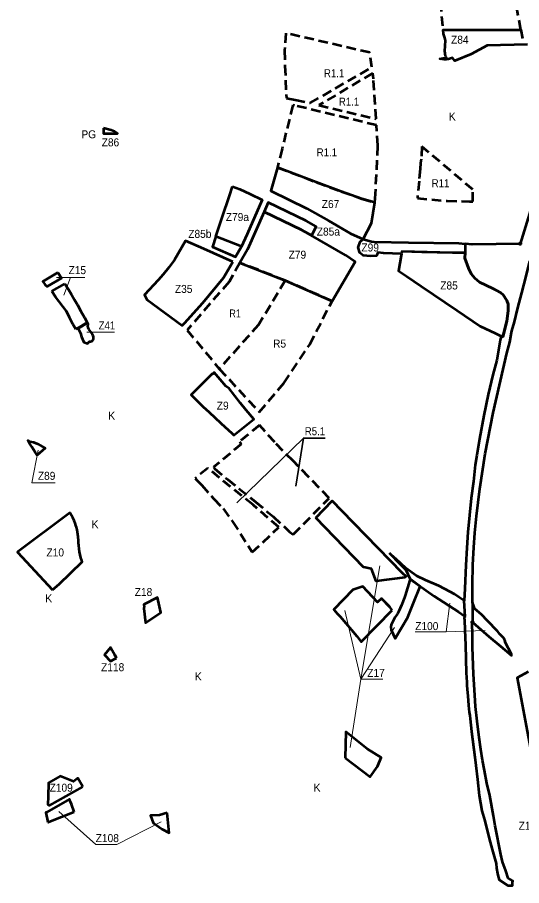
# Model space of a CAD drawing. Extents: x -650246 to -642674, y -1074280 to -1066767.
# Drawn here: x -646713 to -645200, y -1073293 to -1070690 of the extents above; entities that cross this region are included whole.
import ezdxf

# ---------------------------------------------------------------- set-up
doc = ezdxf.new("R2010")
doc.units = 0
doc.header["$LTSCALE"] = 9.6
doc.header["$PDMODE"] = 32
doc.header["$PDSIZE"] = 4.8
doc.linetypes.add('MEDIUM_DASHED', pattern=[4.5, 3, -1.5])
for name, color, linetype, lineweight in [('44', 7, 'Continuous', 53), ('45', 7, 'Continuous', 53), ('46', 7, 'Continuous', 13), ('48', 7, 'Continuous', 13), ('60', 7, 'Continuous', 35), ('61', 7, 'MEDIUM_DASHED', 53), ('62', 7, 'Continuous', 35)]:
    doc.layers.add(name, color=color, linetype=linetype, lineweight=lineweight)

msp = doc.modelspace()

# ---------------------------------------------------------------- linework, layer by layer
at = {"layer": '44'}
msp.add_line((-645369.665, -1071395.694), (-645370.24, -1071411.83), dxfattribs=at)
for points in [[(-645182, -1070771), (-645303, -1070774), (-645351, -1070800), (-645400.05, -1070819.84), (-645407.37, -1070810.95), (-645419.18, -1070815.44), (-645426.36, -1070815.78), (-645432.07, -1070816.05), (-645445.81, -1070814.06), (-645429.993, -1070810.647), (-645424.969, -1070809.563), (-645428.39, -1070806.09), (-645430, -1070790.68), (-645428.73, -1070758.67), (-645430.84, -1070751.43), (-645434.53, -1070738.77), (-645435.711, -1070727.497), (-645202.41, -1070726.571), (-645197.539, -1070753.128)], [(-645078.23, -1070915.65), (-645092.67, -1070979.52), (-645176.14, -1071277.26), (-645204.341, -1071368.19)], [(-645407.045, -1071395.646), (-645499.65, -1071393.3), (-645558.872, -1071391.801), (-645560.11, -1071398.7), (-645614.201, -1071396.844), (-645631.44, -1071394.9), (-645635.795, -1071404.403), (-645653.742, -1071405.36), (-645675.177, -1071403.922), (-645685.098, -1071395.824), (-645690.677, -1071379.721), (-645684.785, -1071362.539), (-645674.947, -1071355.071), (-645650.28, -1071362.07), (-645642.431, -1071362.259), (-645539.738, -1071364.092)], [(-645539.738, -1071364.092), (-645388.619, -1071366.991), (-645369.696, -1071368.676)], [(-645369.67, -1071368.678), (-645369.665, -1071395.694), (-645407.045, -1071395.646)], [(-645204.341, -1071368.19), (-645348.55, -1071370.559), (-645369.67, -1071368.678)], [(-645222.48, -1071606.08), (-645211.27, -1071560.01), (-645199.61, -1071515.68), (-645186.67, -1071465.55), (-645175.06, -1071420.93), (-645167.58, -1071421.19), (-645167.37, -1071415.2), (-645163.56, -1071415.3), (-645164.76, -1071401.79), (-645166.34, -1071384.07)], [(-645560.94, -1071403.441), (-645569.07, -1071449.88), (-645545.817, -1071465.611)], [(-645370.24, -1071411.83), (-645369.665, -1071395.694), (-645407.045, -1071395.646), (-645558.872, -1071391.801), (-645560.11, -1071398.7), (-645560.94, -1071403.441)], [(-645370.24, -1071411.83), (-645359.64, -1071442), (-645351.06, -1071458.3), (-645340.16, -1071471.63), (-645326.29, -1071483.41), (-645286.62, -1071502.67), (-645278.52, -1071506.12)], [(-645326.29, -1071483.41), (-645340.16, -1071471.63), (-645351.06, -1071458.3), (-645359.64, -1071442), (-645370.24, -1071411.83)], [(-645545.817, -1071465.611), (-645501.37, -1071495.68), (-645393.34, -1071568.75)], [(-645279.531, -1071636.404), (-645261.094, -1071645.025), (-645256.02, -1071647.398), (-645244.81, -1071600.61), (-645240.26, -1071569.52), (-645240.82, -1071549.6), (-645244.4, -1071538.48), (-645255.51, -1071521.55), (-645262.36, -1071515.72), (-645286.62, -1071502.67), (-645326.29, -1071483.41)], [(-645278.52, -1071506.12), (-645262.36, -1071515.72), (-645255.51, -1071521.55), (-645244.4, -1071538.48), (-645240.82, -1071549.6), (-645240.26, -1071569.52), (-645244.81, -1071600.61), (-645256.02, -1071647.398), (-645261.094, -1071645.025)], [(-645393.34, -1071568.75), (-645324.17, -1071615.53), (-645279.531, -1071636.404)], [(-645347.551, -1072443.527), (-645347.677, -1072391.355), (-645346.62, -1072330.914), (-645343.458, -1072278.998), (-645339.908, -1072235.158), (-645335.367, -1072185.207), (-645325.498, -1072102.789), (-645309.01, -1071998.147), (-645285.617, -1071875.733), (-645244.798, -1071696.585), (-645235.793, -1071663.703), (-645230.436, -1071634.261), (-645227.905, -1071625.277), (-645222.48, -1071606.08)], [(-645261.094, -1071645.025), (-645264.841, -1071657.687), (-645269.077, -1071687.396), (-645274.868, -1071717.176), (-645286.175, -1071761.228), (-645300.076, -1071820.179), (-645313.153, -1071883.081)], [(-645313.153, -1071883.081), (-645326.343, -1071952.807), (-645334.118, -1072001.954), (-645339.455, -1072031.565), (-645344.819, -1072081.225), (-645351.358, -1072130.815), (-645361.317, -1072232.824), (-645364.435, -1072280.268), (-645366.951, -1072331.609), (-645370.624, -1072401.447), (-645372.228, -1072438.764)], [(-645369.364, -1072485.931), (-645372.228, -1072438.764), (-645373.099, -1072438.135), (-645387.894, -1072427.453), (-645401.441, -1072419.033), (-645414.631, -1072411.611), (-645448.831, -1072394.325), (-645488.64, -1072376.782), (-645515.437, -1072363.447), (-645547.593, -1072340.827), (-645577.33, -1072312.704), (-645579.217, -1072312.425), (-645596.405, -1072296.114)], [(-645596.405, -1072296.114), (-645564.4, -1072328.61), (-645547.72, -1072346.19), (-645534.301, -1072374.332), (-645462.646, -1072425.015)], [(-645462.646, -1072425.015), (-645389.731, -1072471.612), (-645372.013, -1072484.069), (-645369.364, -1072485.931)], [(-645339.904, -1072462.677), (-645342.953, -1072455.042), (-645347.551, -1072443.527), (-645347.292, -1072502.877)], [(-645228.96, -1072600.865), (-645249.9, -1072561.25), (-645248.967, -1072559.511), (-645252.768, -1072552.178), (-645265.009, -1072538.358), (-645272.276, -1072530.154), (-645302.303, -1072499.014), (-645320.805, -1072479.495), (-645339.904, -1072462.677)], [(-645369.364, -1072485.931), (-645372.72, -1072490.314), (-645370.928, -1072496.619), (-645370.755, -1072525.734), (-645368.173, -1072571.881), (-645366.022, -1072654.462), (-645364.524, -1072682.575), (-645364.786, -1072692.977), (-645362.708, -1072714.781)], [(-645338.023, -1072755.969), (-645339.96, -1072721.587), (-645344.152, -1072658.857), (-645347.795, -1072577.893), (-645347.214, -1072540.97), (-645348.253, -1072505.583), (-645347.292, -1072502.877)], [(-645347.292, -1072502.877), (-645346.093, -1072503.921), (-645298.498, -1072545.352)], [(-645298.498, -1072545.352), (-645263.217, -1072574.314), (-645230.845, -1072602.888), (-645228.96, -1072600.865)], [(-645362.708, -1072714.781), (-645361.874, -1072723.527), (-645359.76, -1072752.865), (-645357.272, -1072772.771), (-645355.121, -1072782.993)], [(-645317.65, -1072916.642), (-645322.284, -1072885.085), (-645327.091, -1072848.387), (-645333.718, -1072799.987), (-645338.023, -1072755.969)], [(-645355.121, -1072782.993), (-645354.019, -1072792.454), (-645350.822, -1072830.388), (-645340.345, -1072908.029), (-645337.34, -1072932.073), (-645332.517, -1072974.538), (-645327.554, -1073022.214), (-645319.052, -1073068.6), (-645310.558, -1073098.946), (-645297.395, -1073151.294), (-645288.647, -1073184.518), (-645276.125, -1073226.571), (-645275.269, -1073240.71), (-645272.747, -1073256.762), (-645271.518, -1073261.16)], [(-645304.24, -1072985.372), (-645311.772, -1072947.945), (-645317.65, -1072916.642)], [(-645257.842, -1073221.36), (-645262.388, -1073199.409), (-645279.878, -1073113.356), (-645284.269, -1073083.286), (-645295.788, -1073022.556), (-645304.24, -1072985.372)], [(-645237.524, -1073292.361), (-645227.744, -1073292.735), (-645227.199, -1073283.366), (-645226.847, -1073278.345), (-645239.9, -1073270.025), (-645247.051, -1073248.736), (-645257.842, -1073221.36)], [(-645271.518, -1073261.16), (-645267.525, -1073275.443), (-645241.72, -1073292.2), (-645237.524, -1073292.361)]]:
    msp.add_lwpolyline(points, dxfattribs=at)
for points in [[(-646454.59, -1071021.54), (-646454.59, -1071038), (-646412.54, -1071038.01), (-646415.61, -1071035.4), (-646421.58, -1071031.81), (-646430.91, -1071027.44)], [(-645829.706, -1071343.963), (-645816.714, -1071316.828), (-645846, -1071300), (-645960.34, -1071245.09), (-645972.422, -1071272.568), (-645859.986, -1071326.563)], [(-646117.031, -1071346.48), (-646127.301, -1071378.036), (-646058.719, -1071407.796), (-646051.148, -1071395.208), (-646040.084, -1071376.813)], [(-646652.18, -1071967.73), (-646629.655, -1071981.343), (-646653.198, -1072002.544), (-646657.32, -1071995.98), (-646658.79, -1071993.62), (-646669.31, -1071976.77), (-646676.79, -1071964.97), (-646681.07, -1071958.16), (-646675.99, -1071961.64), (-646663.87, -1071963.26)]]:
    msp.add_lwpolyline(points, close=True, dxfattribs=at)
at = {"layer": '44', "lineweight": 13}
for points in [[(-646599.686, -1072084.891), (-646669.193, -1072084.891), (-646650.508, -1071987.658)], [(-646599.686, -1072084.891), (-646669.193, -1072084.891), (-646650.508, -1071987.658)], [(-645519.31, -1072532.095), (-645425.882, -1072532.095), (-645415.202, -1072445.813), (-645425.882, -1072532.095), (-645309.26, -1072527.964)], [(-645519.31, -1072532.095), (-645425.882, -1072532.095), (-645415.202, -1072445.813), (-645425.882, -1072532.095), (-645309.26, -1072527.964)]]:
    msp.add_lwpolyline(points, dxfattribs=at)
at = {"layer": '44'}
for p in [(-645204.341, -1071368.19), (-645347.292, -1072502.877)]:
    msp.add_point(p, dxfattribs=at)
at = {"layer": '45'}
for p, q in [((-646609.21, -1071510.98), (-646570, -1071488.38)), ((-646609.21, -1071510.98), (-646570, -1071488.38)), ((-646417.787, -1072612.168), (-646414.77, -1072610.61))]:
    msp.add_line(p, q, dxfattribs=at)
for points in [[(-645674.947, -1071355.071), (-645650.09, -1071306.433), (-645640.737, -1071244.963), (-645678.86, -1071233.58), (-645741.09, -1071211.36), (-645816.47, -1071183.63), (-645932.502, -1071139.426), (-645952.419, -1071210.117), (-645844.079, -1071262.487), (-645778.69, -1071299.362), (-645713.428, -1071337.765)], [(-646067.097, -1071196.699), (-646044.944, -1071205.157), (-646015.387, -1071218.854), (-645978.403, -1071236.481), (-646023.652, -1071339.428), (-646035.241, -1071365.795), (-646040.084, -1071376.813), (-646117.031, -1071346.48), (-646098.66, -1071290.03), (-646076.713, -1071225.138)], [(-645768.62, -1071540.17), (-645699.825, -1071422.134), (-645728.054, -1071402.382), (-645806.036, -1071357.564), (-645859.986, -1071326.563), (-645972.422, -1071272.568), (-646022.073, -1071385.273), (-646044.948, -1071425.333), (-645909.13, -1071478.56)], [(-645768.62, -1071540.17), (-645699.825, -1071422.134), (-645728.054, -1071402.382), (-645806.036, -1071357.564), (-645859.986, -1071326.563), (-645972.422, -1071272.568), (-646022.073, -1071385.273), (-646044.948, -1071425.333), (-645909.13, -1071478.56)], [(-646066.165, -1071422.155), (-646153.5, -1071383.85), (-646208.577, -1071360.044), (-646241.68, -1071416.887), (-646258.487, -1071439.265), (-646275.615, -1071460.886), (-646289.976, -1071477.514), (-646330.914, -1071521.11), (-646324, -1071535), (-646217.978, -1071613.552), (-646211.407, -1071606.247), (-646156.471, -1071545.166), (-646094.063, -1071471.007)], [(-646066.165, -1071422.155), (-646153.5, -1071383.85), (-646208.577, -1071360.044), (-646241.68, -1071416.887), (-646258.487, -1071439.265), (-646275.615, -1071460.886), (-646289.976, -1071477.514), (-646330.914, -1071521.11), (-646324, -1071535), (-646217.978, -1071613.552), (-646211.407, -1071606.247), (-646156.471, -1071545.166), (-646094.063, -1071471.007)], [(-646591.65, -1071454.91), (-646635.79, -1071481.6), (-646629.37, -1071491.74), (-646623.18, -1071496.99), (-646580.58, -1071471.48)], [(-646591.65, -1071454.91), (-646635.79, -1071481.6), (-646629.37, -1071491.74), (-646623.18, -1071496.99), (-646580.58, -1071471.48)], [(-646502.39, -1071605.72), (-646530.27, -1071622.79), (-646522.99, -1071636.22), (-646520.32, -1071647.59), (-646513.43, -1071663.64), (-646502.53, -1071667.82), (-646496.06, -1071661.5), (-646492.89, -1071661.75), (-646490.07, -1071660.88), (-646487.36, -1071659.1), (-646485.29, -1071656.53), (-646484.15, -1071653.38), (-646483.97, -1071650.63), (-646484.38, -1071647.41), (-646485.2, -1071644.85), (-646486.31, -1071641.97), (-646487.56, -1071639.23), (-646497.83, -1071624.02), (-646499.829, -1071620.704), (-646500.289, -1071619.291), (-646500.83, -1071615.62), (-646500.34, -1071609.66)], [(-646502.39, -1071605.72), (-646530.27, -1071622.79), (-646522.99, -1071636.22), (-646520.32, -1071647.59), (-646513.43, -1071663.64), (-646502.53, -1071667.82), (-646496.06, -1071661.5), (-646492.89, -1071661.75), (-646490.07, -1071660.88), (-646487.36, -1071659.1), (-646485.29, -1071656.53), (-646484.15, -1071653.38), (-646483.97, -1071650.63), (-646484.38, -1071647.41), (-646485.2, -1071644.85), (-646486.31, -1071641.97), (-646487.56, -1071639.23), (-646497.83, -1071624.02), (-646499.829, -1071620.704), (-646500.289, -1071619.291), (-646500.83, -1071615.62), (-646500.34, -1071609.66)], [(-646102.04, -1071906.4), (-646068.317, -1071937.555), (-646062.91, -1071942.55), (-646002.93, -1071893.984), (-646026.64, -1071867.44), (-646043.49, -1071845.87), (-646077.32, -1071802.59), (-646087, -1071795), (-646104.5, -1071774.86), (-646122.16, -1071754.78), (-646127.12, -1071759.15), (-646127.84, -1071758.53), (-646191.57, -1071821.44), (-646174.69, -1071838.69), (-646156.59, -1071856.53), (-646137.74, -1071873.31)], [(-645817.219, -1072189.975), (-645768.649, -1072139.283), (-645740.45, -1072168.23), (-645559.34, -1072354.42), (-645546.82, -1072365.72), (-645550.41, -1072368.47), (-645636.37, -1072379.57), (-645650.78, -1072342.73), (-645674, -1072338), (-645789.298, -1072218.833)], [(-646606.848, -1072405.785), (-646587.666, -1072389.082), (-646518.208, -1072321.92), (-646519.417, -1072318.408), (-646522.007, -1072309.932), (-646524.282, -1072300.849), (-646526, -1072292.201), (-646527.5, -1072282.657), (-646528.566, -1072273.308), (-646529.182, -1072265.941), (-646529.607, -1072258.124), (-646530.188, -1072247.442), (-646530.892, -1072239.747), (-646531.93, -1072232.861), (-646533.286, -1072226.031), (-646535.344, -1072217.844), (-646536.772, -1072213.218), (-646539.168, -1072206.122), (-646539.168, -1072206.122), (-646542.484, -1072197.985), (-646546.09, -1072190.428), (-646549.793, -1072183.38), (-646554.56, -1072175.629), (-646555.051, -1072174.933), (-646563.299, -1072181.091), (-646710.684, -1072291.133), (-646712.634, -1072292.59)], [(-645503.98, -1072395.64), (-645532.75, -1072375.41), (-645535.05, -1072376.72), (-645549.6, -1072423.39), (-645551.54, -1072428.66), (-645559.92, -1072451.41), (-645568.38, -1072469.68), (-645572.13, -1072477.78), (-645579.92, -1072489.22), (-645581.13, -1072491), (-645591.06, -1072511.06), (-645592.08, -1072517.43), (-645591.03, -1072526.14), (-645579.76, -1072551.45), (-645541.09, -1072487.98), (-645533.15, -1072468.21), (-645524.87, -1072447.61)], [(-645588.78, -1072467), (-645594.83, -1072458.48), (-645596.43, -1072455.42), (-645620.56, -1072432), (-645632.1, -1072442.93), (-645676.53, -1072396.16), (-645706.039, -1072405.769), (-645763.06, -1072465.26), (-645753.128, -1072476.383), (-645744.38, -1072486.18), (-645726.95, -1072505.7), (-645709.92, -1072526.3), (-645694.51, -1072544.93), (-645680.87, -1072561.42)], [(-645588.78, -1072467), (-645594.83, -1072458.48), (-645620.56, -1072432), (-645632.1, -1072442.93), (-645676.53, -1072396.16), (-645706.039, -1072405.769), (-645763.06, -1072465.26), (-645753.128, -1072476.383), (-645744.38, -1072486.18), (-645726.95, -1072505.7), (-645709.92, -1072526.3), (-645694.51, -1072544.93), (-645680.87, -1072561.42)], [(-646333.34, -1072461.67), (-646328.45, -1072504.81), (-646282.47, -1072474.34), (-646292.44, -1072428.89), (-646333.33, -1072450.12), (-646332.68, -1072456.19)], [(-646333.34, -1072461.67), (-646328.45, -1072504.81), (-646282.47, -1072474.34), (-646292.44, -1072428.89), (-646333.33, -1072450.12), (-646332.68, -1072456.19)], [(-645729.36, -1072909.65), (-645654.16, -1072966.3), (-645632.23, -1072935.28), (-645620.92, -1072908.65), (-645663.52, -1072882.58), (-645726.9, -1072831.5)], [(-645729.36, -1072909.65), (-645654.16, -1072966.3), (-645632.23, -1072935.28), (-645620.92, -1072908.65), (-645663.52, -1072882.58), (-645726.9, -1072831.5)], [(-646516.7, -1072996.65), (-646531.46, -1072970.12), (-646544.68, -1072980.62), (-646584.23, -1072964.22), (-646619.48, -1072984.34), (-646620.71, -1073025.49), (-646621.44, -1073049.79), (-646616.55, -1073052.21)], [(-646516.7, -1072996.65), (-646531.46, -1072970.12), (-646544.68, -1072980.62), (-646584.23, -1072964.22), (-646619.48, -1072984.34), (-646620.71, -1073025.49), (-646621.44, -1073049.79), (-646616.55, -1073052.21)]]:
    msp.add_lwpolyline(points, close=True, dxfattribs=at)
for points in [[(-646570, -1071488.38), (-646559.53, -1071505.12), (-646550.23, -1071520.88), (-646541.14, -1071536.3), (-646532.04, -1071551.72), (-646521.8, -1071570.34), (-646511.47, -1071589.11), (-646503.31, -1071603.95), (-646531.2, -1071621.07), (-646537.28, -1071624.8)], [(-646570, -1071488.38), (-646559.53, -1071505.12), (-646550.23, -1071520.88), (-646541.14, -1071536.3), (-646532.04, -1071551.72), (-646521.8, -1071570.34), (-646511.47, -1071589.11), (-646503.31, -1071603.95), (-646531.2, -1071621.07), (-646537.28, -1071624.8)], [(-646537.28, -1071624.8), (-646545.89, -1071609.07), (-646555.78, -1071589.66), (-646565.17, -1071570.4), (-646598.63, -1071527.8), (-646609.21, -1071510.98)], [(-646537.28, -1071624.8), (-646545.89, -1071609.07), (-646555.78, -1071589.66), (-646565.17, -1071570.4), (-646598.63, -1071527.8), (-646609.21, -1071510.98)], [(-646420.36, -1072601.78), (-646427.95, -1072588.07), (-646432.57, -1072579.75), (-646433.36, -1072578.45), (-646451.458, -1072601.008), (-646433.024, -1072620.04), (-646417.787, -1072612.168)], [(-646414.77, -1072610.61), (-646419.11, -1072602.03), (-646419.47, -1072601.31), (-646419.02, -1072604.18), (-646420.36, -1072601.78)], [(-645180.05, -1072651.77), (-645213.34, -1072669.98), (-645174.13, -1072877.93)], [(-646542.62, -1073071.1), (-646550.01, -1073048.55), (-646552.79, -1073041.53), (-646555.79, -1073033.92), (-646624.69, -1073072.66), (-646626.967, -1073073.918), (-646621.38, -1073102.66)], [(-646542.62, -1073071.1), (-646550.01, -1073048.55), (-646552.79, -1073041.53), (-646555.79, -1073033.92), (-646624.69, -1073072.66), (-646626.967, -1073073.918), (-646621.38, -1073102.66)], [(-646542.62, -1073071.1), (-646550.01, -1073048.55), (-646552.79, -1073041.53), (-646555.79, -1073033.92), (-646624.69, -1073072.66), (-646626.967, -1073073.918), (-646621.38, -1073102.66)], [(-646542.62, -1073071.1), (-646550.01, -1073048.55), (-646552.79, -1073041.53), (-646555.79, -1073033.92), (-646624.69, -1073072.66), (-646626.967, -1073073.918), (-646621.38, -1073102.66)], [(-646621.38, -1073102.66), (-646620.19, -1073102.14), (-646618.56, -1073101.42), (-646542.62, -1073071.1)], [(-646621.38, -1073102.66), (-646620.19, -1073102.14), (-646618.56, -1073101.42), (-646542.62, -1073071.1)], [(-646621.38, -1073102.66), (-646620.19, -1073102.14), (-646618.56, -1073101.42), (-646542.62, -1073071.1)], [(-646621.38, -1073102.66), (-646620.19, -1073102.14), (-646618.56, -1073101.42), (-646542.62, -1073071.1)], [(-646262.94, -1073074.15), (-646285.77, -1073081.01), (-646312.87, -1073082.4), (-646305.18, -1073104.8), (-646278.38, -1073123.25)], [(-646262.94, -1073074.15), (-646285.77, -1073081.01), (-646312.87, -1073082.4), (-646305.18, -1073104.8), (-646278.38, -1073123.25)], [(-646278.38, -1073123.25), (-646257.09, -1073134.01), (-646262.94, -1073074.15)], [(-646278.38, -1073123.25), (-646257.09, -1073134.01), (-646262.94, -1073074.15)]]:
    msp.add_lwpolyline(points, dxfattribs=at)
at = {"layer": '46'}
for p, q in [((-646510.087, -1071469.269), (-646595.257, -1071469.269)), ((-646510.087, -1071469.269), (-646595.257, -1071469.269)), ((-646421.181, -1071633.007), (-646504.11, -1071633.007)), ((-646421.181, -1071633.007), (-646504.11, -1071633.007)), ((-645682.434, -1072673.943), (-645625.498, -1072333.934)), ((-645682.434, -1072673.943), (-645729.938, -1072467.657)), ((-645682.434, -1072673.943), (-645729.938, -1072467.657)), ((-645682.434, -1072673.943), (-645581.338, -1072519.311)), ((-645682.434, -1072673.943), (-645714.669, -1072878.528)), ((-645682.434, -1072673.943), (-645714.669, -1072878.528)), ((-645616.267, -1072673.943), (-645682.434, -1072673.943))]:
    msp.add_line(p, q, dxfattribs=at)
for points in [[(-646510.087, -1071469.269), (-646553.419, -1071469.269), (-646572.844, -1071522.353)], [(-646510.087, -1071469.269), (-646553.419, -1071469.269), (-646572.844, -1071522.353)], [(-646588.523, -1073070.963), (-646477.555, -1073169.273), (-646414.561, -1073169.273), (-646281.126, -1073101.085)], [(-646588.523, -1073070.963), (-646477.555, -1073169.273), (-646414.561, -1073169.273), (-646281.126, -1073101.085)]]:
    msp.add_lwpolyline(points, dxfattribs=at)
at = {"layer": '61'}
msp.add_line((-645909.13, -1071478.56), (-646044.948, -1071425.333), dxfattribs=at)
for points in [[(-645444.47, -1070643.85), (-645435.711, -1070727.497), (-645301.722, -1070726.965), (-645202.41, -1070726.571), (-645221.272, -1070623.729)], [(-646044.948, -1071425.333), (-646077.593, -1071482.499), (-646203.387, -1071627.322), (-646107, -1071743)]]:
    msp.add_lwpolyline(points, dxfattribs=at)
for points in [[(-645905.795, -1070931.641), (-645879, -1070937), (-645834, -1070946), (-645649.136, -1070839.223), (-645655.04, -1070795.257), (-645907.061, -1070736.979), (-645911.345, -1070788.463), (-645910.048, -1070834.649)], [(-645646.718, -1070857.232), (-645808, -1070953), (-645636.529, -1070993.874), (-645644.425, -1070874.306)], [(-645881.661, -1070953.494), (-645885.966, -1070952.452), (-645918.57, -1071083.449), (-645932.502, -1071139.426), (-645816.47, -1071183.63), (-645741.09, -1071211.36), (-645678.86, -1071233.58), (-645640.737, -1071244.963), (-645638.935, -1071233.122), (-645631.241, -1071073.956), (-645635.256, -1071013.15)], [(-645512.84, -1071231.9), (-645423.08, -1071239.85), (-645356.794, -1071241.776), (-645346.67, -1071242.07), (-645346.31, -1071206.07), (-645498.931, -1071076.631), (-645500.94, -1071115.24), (-645503.08, -1071126.98), (-645504.79, -1071144.18), (-645507.84, -1071180.326)], [(-645909.13, -1071478.56), (-645989, -1071611), (-646107, -1071743), (-645987.026, -1071872.902), (-645913.616, -1071786.041), (-645835.644, -1071670.191), (-645768.62, -1071540.17)], [(-645896.15, -1072231.57), (-645884.949, -1072239.96), (-645777.057, -1072130.664), (-645839.31, -1072066.947), (-645885.655, -1072019.486), (-645940.8, -1071963.54), (-645986.568, -1071912.301), (-646046.78, -1071962.265), (-646041.113, -1071969.094), (-646124.568, -1072038.344), (-646121.403, -1072042.471), (-646081.78, -1072075), (-645998.22, -1072142.19), (-645945, -1072186)], [(-646141.703, -1072041.072), (-646178.915, -1072071.95), (-646159.66, -1072092.31), (-646123.06, -1072133.18), (-646095.44, -1072162.47), (-646067.08, -1072201.18), (-646008.065, -1072293.22), (-645928.101, -1072218.151), (-646005.793, -1072151.499)]]:
    msp.add_lwpolyline(points, close=True, dxfattribs=at)
at = {"layer": '62'}
msp.add_line((-645854.421, -1071950.737), (-645877.767, -1072095.485), dxfattribs=at)
msp.add_lwpolyline([(-645789.051, -1071950.737), (-645854.421, -1071950.737), (-646054.422, -1072145.291)], dxfattribs=at)

# ---------------------------------------------------------------- texts
at = {"layer": '44', "width": 0.95}
for s, p in [('Z84', (-645411.663, -1070768.505)), ('Z84', (-645411.663, -1070768.505)), ('Z86', (-646459.658, -1071076.35)), ('Z86', (-646459.658, -1071076.35)), ('Z85b', (-646199.969, -1071350.698)), ('Z85a', (-645814.405, -1071343.847)), ('Z85a', (-645814.405, -1071343.847)), ('Z99', (-645680.485, -1071391.504)), ('Z99', (-645680.485, -1071391.504)), ('Z85', (-645444.048, -1071505.433)), ('Z85', (-645444.048, -1071505.433)), ('Z89', (-646651.144, -1072076.059)), ('Z89', (-646651.144, -1072076.059)), ('Z100', (-645519.262, -1072526.583)), ('Z100', (-645519.262, -1072526.583))]:
    msp.add_text(s, height=24, dxfattribs=at).set_placement(p)
at = {"layer": '46'}
for s, width, p in [('Z67', 0.95, (-645799.458, -1071261.304)), ('Z67', 0.95, (-645799.458, -1071261.304)), ('Z79a', 0.95, (-646087.322, -1071300.282)), ('Z79', 0.95, (-645898.897, -1071413.165)), ('Z79', 0.95, (-645898.897, -1071413.165)), ('Z15', 0.95, (-646559.155, -1071459.428)), ('Z15', 0.95, (-646559.155, -1071459.428)), ('Z35', 0.95, (-646239.99, -1071515.768)), ('Z35', 0.95, (-646239.99, -1071515.768)), ('Z41', 0.9, (-646468.869, -1071625.297)), ('Z41', 0.9, (-646468.869, -1071625.297)), ('Z9', 0.95, (-646114.385, -1071865.725)), ('Z10', 0.95, (-646625.207, -1072305.81)), ('Z18', 0.95, (-646360.479, -1072424.402)), ('Z118', 0.95, (-646461.466, -1072649.857)), ('Z17', 0.95, (-645663.172, -1072666.966)), ('Z109', 0.95, (-646615.842, -1073011.142)), ('Z109', 0.95, (-646615.842, -1073011.142)), ('Z115', 0.95, (-645208.897, -1073125.218)), ('Z108', 0.95, (-646477.565, -1073162.229)), ('Z108', 0.95, (-646477.565, -1073162.229))]:
    msp.add_text(s, height=24, dxfattribs=dict(at, width=width)).set_placement(p)
at = {"layer": '48'}
for p in [(-645418.824, -1070998.868), (-645418.824, -1070998.868), (-646440.579, -1071895.779), (-646490.42, -1072221.403), (-646629.338, -1072443.411), (-646180.786, -1072677.559), (-646180.786, -1072677.559), (-645824.362, -1073011.011), (-645824.362, -1073011.011)]:
    msp.add_text('K', height=24, dxfattribs=at).set_placement(p)
at = {"layer": '60', "width": 0.95}
msp.add_text('PG', height=24, dxfattribs=at).set_placement((-646520.539, -1071052.252))
msp.add_text('PG', height=24, dxfattribs=at).set_placement((-646520.539, -1071052.252))
at = {"layer": '62'}
for s, width, p in [('R1.1', 0.9, (-645792.947, -1070869.095)), ('R1.1', 0.9, (-645748.253, -1070954.32)), ('R1.1', 0.9, (-645814.758, -1071106.298)), ('R11', 0.9, (-645469.881, -1071198.853)), ('R1', 0.85, (-646076.842, -1071589.396)), ('R5', 0.95, (-645945.557, -1071679.725)), ('R5', 0.95, (-645945.557, -1071679.725)), ('R5.1', 0.9, (-645850.499, -1071942.459))]:
    msp.add_text(s, height=24, dxfattribs=dict(at, width=width)).set_placement(p)

doc.saveas('drawing.dxf')
